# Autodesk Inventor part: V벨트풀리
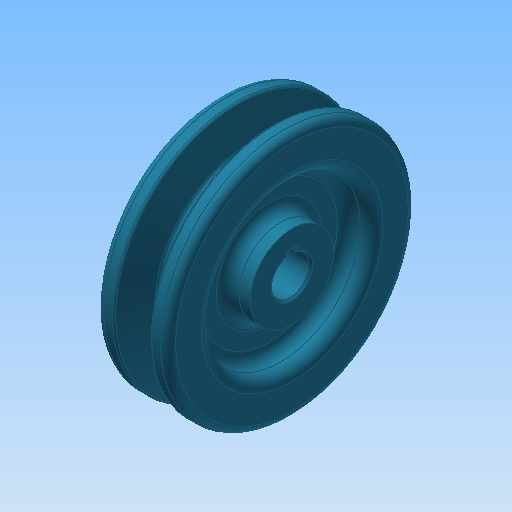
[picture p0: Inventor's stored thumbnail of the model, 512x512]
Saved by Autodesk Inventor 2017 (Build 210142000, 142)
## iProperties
Created: 2015-11
Part Number: V벨트풀리
Material: 강철, 탄소
Document SubType Name: Modeling
Designer: mduedu
Density: 1 g/cm^3
Appearance: 터키옥색
Author: mduedu
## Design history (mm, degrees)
sketch "스케치1"
  geometry: L1 (-9.5, 0)-(9.5, 0); L2 (0, 0)-(0, 32.7); L3 (-4.825, 32.7)-(-9.5, 32.7); L4 (-9.5, 32.7)-(-9.5, 0); L5 (0, 23.7)-(-2.074, 23.7); L6 (-2.074, 23.7)-(-4.825, 32.7); L7 (4.825, 32.7)-(9.5, 32.7); L8 (9.5, 32.7)-(9.5, 0); L9 (0, 23.7)-(2.074, 23.7); L10 (2.074, 23.7)-(4.825, 32.7); L11 (-9.5, 30)-(9.5, 30); 3 further points
  constraints: 22 end point, 7 point on line, 4 perpendicular, 3 symmetric about line, 1 coincident, 1 horizontal, 1 horizontal alignment, 1 midpoint, 1 vertical
  dimensions: "d0" = 19 distance of L1.start L1.end; "d2" = 65.4 diameter of L2.end L1 (derived); "d3" = 34 deg angle of L10 L6; "d4" = 6.3 distance between parallel lines of L11 L9; "d5" = 2.7 distance between parallel lines of L7 L11; "d6" = 8 distance of point (4, 30) point (-4, 30); "d7" = 60 diameter of L11 L1
revolve "회전1" sketch "스케치1" stored, may be unused: angle "d8" = 90 deg
sketch "스케치2"
  geometry: C1 r 21 at (0, 0); C2 r 11 at (0, 0); 1 further point
  constraints: 2 centre point, 2 coincident
  dimensions: "d9" = 42 diameter of C1; "d10" = 22 diameter of C2
extrude "돌출1" cut sketch "스케치2" distance "d11" = 6; taper "d12" = 0 deg
fillet "모깎기1" dims "d13" = 3
fillet "모깎기2" dims "d14" = 3
fillet "모깎기3" dims "d15" = 1, "d16" = 0.5, "d17" = 2
hole "구멍1" diameter "d20" = 10; stored, may be unused: countersink angle "d24" = 90 deg, drill point angle "d26" = 118 deg; dims "d18" = 10, "d19" = 10, "d21" = 6, "d22" = 4, "d23" = 2, "d25" = 8
sketch "스케치3"
  geometry: L1 (-1.5, 0)-(1.5, 0); L2 (1.5, 0)-(1.5, 6.4); L3 (1.5, 6.4)-(-1.5, 6.4); L4 (-1.5, 6.4)-(-1.5, 0); 2 further points
  constraints: 8 end point, 2 parallel, 1 coincident, 1 horizontal, 1 midpoint, 1 perpendicular
  dimensions: "d27" = 3 distance of L2.end L3.end; "d29" = 6.4 distance of L3.end L1.start
extrude "돌출2" cut sketch "스케치3" stored distance "d30" = 6; taper "d31" = 0 deg
chamfer "모따기1" distance "d32" = 0.5; stored, may be unused: second distance "d33" = 2, angle "d34" = 45 deg
node "솔리드1"
mirror "대칭1"
